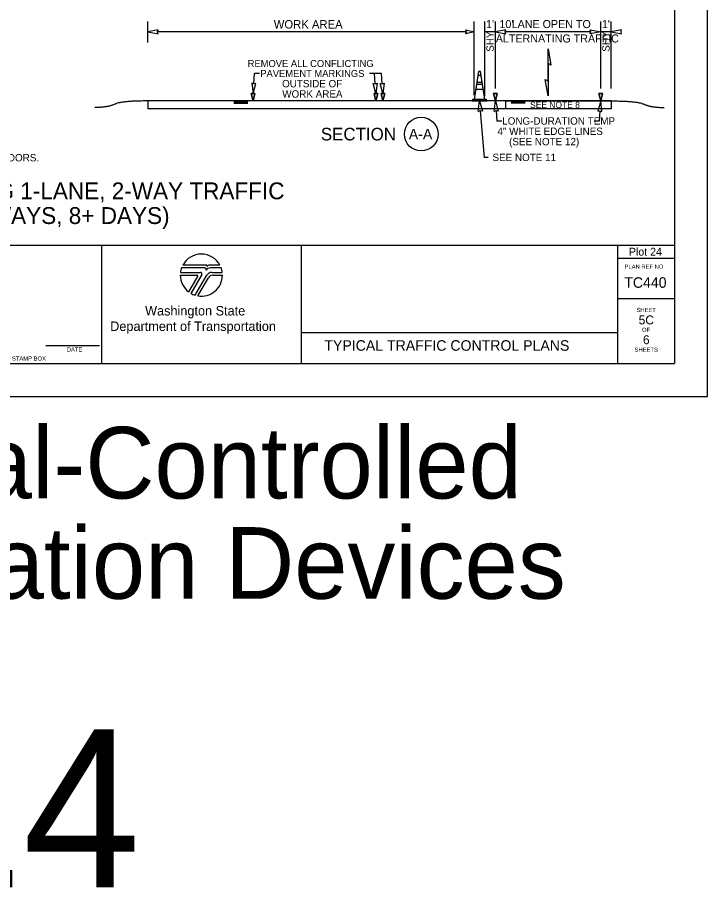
# Model space of a CAD drawing. Extents: x 99982 to 100176, y 99905 to 100011.
# Drawn here: x 100069.51 to 100076.06, y 99935.01 to 99943.29 of the extents above; entities that cross this region are included whole.
import ezdxf

# ---------------------------------------------------------------- set-up
doc = ezdxf.new("R2010")
doc.units = 0
for name, color, linetype in [('SH_DE_DetailHeading1Text', 7, 'Continuous'), ('SH_GI_GeneralNotesBodyText', 7, 'Continuous'), ('SH_GI_PlotLimits', 7, 'Continuous'), ('SH_GI_SheetBorder', 7, 'Continuous'), ('SH_GI_SheetLocationText', 7, 'Continuous'), ('SH_GI_SheetTextInCells', 7, 'Continuous'), ('SH_GI_TitleBlockText', 7, 'Continuous'), ('SH_GI_WSDOTLogo', 7, 'Continuous'), ('TR_WZ_TrafficConeElev', 7, 'Continuous'), ('TR_WZ_WorkZoneDetails', 7, 'Continuous'), ('TR_WZ_WorkZoneTextCurrent', 7, 'Continuous')]:
    doc.layers.add(name, color=color, linetype=linetype)

msp = doc.modelspace()

# ---------------------------------------------------------------- linework, layer by layer
at = {"layer": 'SH_GI_PlotLimits'}
msp.add_lwpolyline([(100059.0625, 99939.6875), (100076.0625, 99939.6875), (100076.0625, 99950.6875), (100059.0625, 99950.6875)], close=True, dxfattribs=at)
at = {"layer": 'SH_GI_SheetBorder'}
for p, q in [((100075.75, 99950.375), (100075.75, 99940)), ((100060, 99941.1259), (100075.75, 99941.1259)), ((100070.3089, 99941.1259), (100070.3089, 99940)), ((100072.2055, 99941.1259), (100072.2055, 99940)), ((100075.2079, 99941.1259), (100075.2079, 99940)), ((100075.2079, 99941.0008), (100075.75, 99941.0008)), ((100075.2079, 99940.6176), (100075.75, 99940.6176)), ((100072.2055, 99940.2955), (100075.2079, 99940.2955)), ((100069.7797, 99940.1733), (100070.2914, 99940.1733)), ((100060, 99940), (100075.75, 99940))]:
    msp.add_line(p, q, dxfattribs=at)
at = {"layer": 'SH_GI_WSDOTLogo'}
for p, q in [((100071.303, 99940.9354), (100071.0815, 99940.9354)), ((100071.433, 99940.9354), (100071.3351, 99940.9354)), ((100071.0572, 99940.84), (100071.2148, 99940.84)), ((100071.059, 99940.8661), (100071.2496, 99940.8661)), ((100071.2894, 99940.9094), (100071.0697, 99940.9094)), ((100071.261, 99940.8464), (100071.1567, 99940.6672)), ((100071.1989, 99940.6487), (100071.3089, 99940.839)), ((100071.343, 99940.9094), (100071.3429, 99940.9094)), ((100071.4448, 99940.9094), (100071.343, 99940.9094)), ((100071.3558, 99940.8661), (100071.4555, 99940.8661)), ((100071.3655, 99940.8394), (100071.4572, 99940.8394)), ((100071.222, 99940.8277), (100071.1364, 99940.6807)), ((100071.2244, 99940.6428), (100071.3242, 99940.8156))]:
    msp.add_line(p, q, dxfattribs=at)
for centre, radius, start, end in [((100071.2572, 99940.84), 0.2, 28.47865, 151.53204), ((100071.303, 99940.9263), 0.00903, 329.87418, 90.00328), ((100071.3352, 99940.9066), 0.0287, 90.00721, 148.16763), ((100071.2572, 99940.84), 0.2, 179.99864, 232.84327), ((100071.2572, 99940.84), 0.2, 159.69598, 172.50569), ((100071.2149, 99940.8318), 0.0082, 329.74356, 90), ((100071.2572, 99940.84), 0.2, 260.54554, 359.80857), ((100071.2497, 99940.853), 0.0131, 329.76834, 90), ((100071.2894, 99940.8946), 0.0148, 327.8418, 89.99855), ((100071.3429, 99940.861), 0.0484, 89.99529, 147.82376), ((100071.3558, 99940.8119), 0.0542, 90, 149.99738), ((100071.3654, 99940.7918), 0.0476, 90, 150.05432), ((100071.2572, 99940.84), 0.2, 7.49431, 20.29406), ((100071.2572, 99940.84), 0.2, 239.79292, 253.0448)]:
    msp.add_arc(centre, radius, start, end, dxfattribs=at)
at = {"layer": 'TR_WZ_TrafficConeElev'}
for p, q in [((100073.8828, 99942.7369), (100073.8728, 99942.6719)), ((100073.8728, 99942.6719), (100073.923, 99942.6719)), ((100073.913, 99942.7369), (100073.8828, 99942.7369)), ((100073.923, 99942.6719), (100073.913, 99942.7369)), ((100073.8697, 99942.6519), (100073.8628, 99942.6069)), ((100073.8628, 99942.6069), (100073.9329, 99942.6069)), ((100073.926, 99942.6519), (100073.8697, 99942.6519)), ((100073.9329, 99942.6069), (100073.926, 99942.6519)), ((100073.8335, 99942.5094), (100073.8285, 99942.5044)), ((100073.8285, 99942.5044), (100073.8285, 99942.4944)), ((100073.8285, 99942.4944), (100073.9673, 99942.4944)), ((100073.8479, 99942.5094), (100073.8335, 99942.5094)), ((100073.9673, 99942.5044), (100073.9623, 99942.5094)), ((100073.9673, 99942.4944), (100073.9673, 99942.5044))]:
    msp.add_line(p, q, dxfattribs=at)
msp.add_lwpolyline([(100073.8479, 99942.5094), (100073.9479, 99942.5094), (100073.9073, 99942.7744), (100073.8885, 99942.7744)], close=True, dxfattribs=at)
msp.add_lwpolyline([(100073.8479, 99942.5094), (100073.9479, 99942.5094), (100073.9073, 99942.7744), (100073.8885, 99942.7744)], close=True, dxfattribs=at)
msp.add_lwpolyline([(100073.9623, 99942.5094), (100073.9479, 99942.5094), (100073.8479, 99942.5094)], dxfattribs=at)
at = {"layer": 'TR_WZ_WorkZoneDetails'}
for p, q in [((100070.7479, 99943.0504), (100070.7479, 99943.2504)), ((100073.8479, 99942.5494), (100073.8479, 99943.2504)), ((100073.9479, 99942.5394), (100073.9479, 99943.2504)), ((100074.0479, 99942.6142), (100074.0479, 99943.2504)), ((100075.0479, 99942.6142), (100075.0479, 99943.2504)), ((100075.1479, 99942.6142), (100075.1479, 99943.2504)), ((100073.7729, 99943.1504), (100070.8416, 99943.1504)), ((100074.0479, 99943.1504), (100073.9479, 99943.1504)), ((100074.9542, 99943.1504), (100074.1416, 99943.1504)), ((100075.1479, 99943.1504), (100075.0479, 99943.1504)), ((100074.5479, 99942.8508), (100074.5479, 99942.682)), ((100074.5479, 99942.682), (100074.5479, 99942.8508)), ((100071.7553, 99942.6576), (100071.763, 99942.7552)), ((100071.8092, 99942.7552), (100071.763, 99942.7552)), ((100072.966, 99942.7552), (100072.8531, 99942.7552)), ((100072.9071, 99942.6576), (100072.8993, 99942.7552)), ((100072.9737, 99942.6576), (100072.966, 99942.7552)), ((100070.7479, 99942.4944), (100070.7479, 99942.4194)), ((100075.1479, 99942.4944), (100070.7479, 99942.4944)), ((100075.1479, 99942.4944), (100075.1479, 99942.4194)), ((100075.1479, 99942.4194), (100070.7479, 99942.4194)), ((100071.5649, 99942.4891), (100071.6979, 99942.4891)), ((100071.5649, 99942.4835), (100071.6979, 99942.4835)), ((100071.5649, 99942.4779), (100071.6979, 99942.4779)), ((100071.5649, 99942.4726), (100071.6979, 99942.4726)), ((100074.3309, 99942.4887), (100074.1979, 99942.4887)), ((100074.3309, 99942.4831), (100074.1979, 99942.4831)), ((100074.3309, 99942.4774), (100074.1979, 99942.4774)), ((100074.3309, 99942.4722), (100074.1979, 99942.4722)), ((100073.9053, 99942.4009), (100073.9406, 99941.9574)), ((100074.0553, 99942.4009), (100074.0631, 99942.3034)), ((100075.0404, 99942.4009), (100075.0327, 99942.3034)), ((100074.1092, 99942.3034), (100074.0631, 99942.3034)), ((100075.0327, 99942.3034), (100074.9865, 99942.3034)), ((100073.9806, 99941.9574), (100073.9406, 99941.9574))]:
    msp.add_line(p, q, dxfattribs=at)
for points in [[(100070.7479, 99943.1504), (100070.8461, 99943.1312), (100070.8416, 99943.1504), (100070.8461, 99943.1697)], [(100073.8479, 99943.1504), (100073.7693, 99943.1312), (100073.7729, 99943.1504), (100073.7693, 99943.1697)], [(100074.0479, 99943.1504), (100074.1462, 99943.1312), (100074.1416, 99943.1504), (100074.1462, 99943.1697)], [(100075.0479, 99943.1504), (100074.9496, 99943.1312), (100074.9542, 99943.1504), (100074.9496, 99943.1697)], [(100075.1479, 99943.1504), (100075.2462, 99943.1312), (100075.2416, 99943.1504), (100075.2462, 99943.1697)], [(100074.5479, 99942.9884), (100074.5749, 99942.8352), (100074.5479, 99942.8508)], [(100071.7478, 99942.5642), (100071.7748, 99942.6606), (100071.7552, 99942.6576), (100071.7363, 99942.6637)], [(100072.9145, 99942.5642), (100072.8875, 99942.6606), (100072.9071, 99942.6576), (100072.926, 99942.6637)], [(100072.9812, 99942.5642), (100072.9542, 99942.6606), (100072.9738, 99942.6576), (100072.9926, 99942.6637)], [(100074.5479, 99942.5444), (100074.5209, 99942.6976), (100074.5479, 99942.682)], [(100071.7479, 99942.4944), (100071.7312, 99942.5642), (100071.7645, 99942.5642)], [(100072.9145, 99942.4944), (100072.8978, 99942.5642), (100072.9312, 99942.5642)], [(100072.9812, 99942.4944), (100072.9645, 99942.5642), (100072.9978, 99942.5642)], [(100073.8979, 99942.4944), (100073.9248, 99942.3979), (100073.9053, 99942.4009), (100073.8864, 99942.3949)], [(100074.0479, 99942.4944), (100074.0312, 99942.5642), (100074.0645, 99942.5642)], [(100074.0479, 99942.4944), (100074.0748, 99942.3979), (100074.0553, 99942.4009), (100074.0364, 99942.3949)], [(100074.1479, 99942.4944), (100075.1479, 99942.4944), (100075.1479, 99942.4194), (100074.1479, 99942.4194)], [(100074.1479, 99942.4944), (100075.1479, 99942.4944), (100075.1479, 99942.4194), (100074.1479, 99942.4194)], [(100075.0479, 99942.4944), (100075.0209, 99942.3979), (100075.0405, 99942.4009), (100075.0593, 99942.3949)], [(100075.0479, 99942.4944), (100075.0312, 99942.5642), (100075.0645, 99942.5642)]]:
    msp.add_lwpolyline(points, close=True, dxfattribs=at)
for points in [[(100071.7645, 99942.5642), (100071.7312, 99942.5642), (100071.7479, 99942.4944), (100071.7645, 99942.5642)], [(100072.9312, 99942.5642), (100072.8978, 99942.5642), (100072.9145, 99942.4944), (100072.9312, 99942.5642)], [(100072.9978, 99942.5642), (100072.9645, 99942.5642), (100072.9812, 99942.4944), (100072.9978, 99942.5642)], [(100074.0645, 99942.5642), (100074.0312, 99942.5642), (100074.0479, 99942.4944), (100074.0645, 99942.5642)], [(100075.0645, 99942.5642), (100075.0312, 99942.5642), (100075.0479, 99942.4944), (100075.0645, 99942.5642)]]:
    msp.add_lwpolyline(points, dxfattribs=at)
msp.add_circle((100073.3444, 99942.1794), 0.16, dxfattribs=at)
for points in [[(100070.7479, 99942.4944), (100070.4967, 99942.4944), (100070.3712, 99942.4322), (100070.2457, 99942.4322)], [(100075.1479, 99942.4944), (100075.399, 99942.4945), (100075.5245, 99942.4324), (100075.65, 99942.4325)]]:
    msp.add_open_spline(points, degree=2, dxfattribs=at)

# ---------------------------------------------------------------- texts
at = {"layer": 'SH_DE_DetailHeading1Text'}
for s, p in [('ADVANCED TEMPORARY SIGNAL-CONTROLLED ALTERNATING 1-LANE, 2-WAY TRAFFIC', (100062.9401, 99941.5606)), ('25 WZSL + CHANNELIZING DEVICES (30 MPH HIGHWAYS, 8+ DAYS)', (100064.0241, 99941.3259))]:
    msp.add_text(s, height=0.16, rotation=360, dxfattribs=at).set_placement(p)
at = {"layer": 'SH_GI_GeneralNotesBodyText'}
msp.add_text('ROADWAY WIDTH RESTRICTIONS. 30 DAY NOTICE REQUIRED ON MAJOR FREIGHT CORRIDORS.', height=0.07, rotation=360, dxfattribs=at).set_placement((100065.3222, 99941.9206))
at = {"layer": 'SH_GI_SheetBorder'}
msp.add_text('PLAN REF NO', height=0.040032, dxfattribs=at).set_placement((100075.2747, 99940.9008))
at = {"layer": 'SH_GI_SheetLocationText'}
for s, height, p in [('Plot 24', 0.075, (100075.3164, 99941.025)), (' Temp Signal-Controlled', 0.68, (100064.4951, 99938.7191)), ('Alt Traffic w/ Channelization Devices', 0.68, (100059.9592, 99937.7671)), ('Plot 24', 1.5, (100064.4341, 99935.0267))]:
    msp.add_text(s, height=height, dxfattribs=at).set_placement(p)
at = {"layer": 'SH_GI_SheetTextInCells'}
for s, height, p in [('Washington State', 0.090072, (100070.7229, 99940.4571)), ('SHEET', 0.04003, (100075.3877, 99940.4896)), ('Department of Transportation', 0.090072, (100070.3916, 99940.3101)), ('OF', 0.04003, (100075.4406, 99940.3008)), ('DATE', 0.04003, (100069.9794, 99940.1141)), ('SHEETS', 0.04003, (100075.3698, 99940.112)), ('P.E. STAMP BOX', 0.040032, (100069.339, 99940.0286))]:
    msp.add_text(s, height=height, dxfattribs=at).set_placement(p)
at = {"layer": 'SH_GI_TitleBlockText'}
for s, height, p in [('TC440', 0.1, (100075.2718, 99940.72)), ('5C', 0.085, (100075.4084, 99940.3723)), ('6', 0.085, (100075.4493, 99940.1843)), ('TYPICAL TRAFFIC CONTROL PLANS', 0.1, (100072.4251, 99940.1224))]:
    msp.add_text(s, height=height, dxfattribs=at).set_placement(p)
at = {"layer": 'TR_WZ_WorkZoneDetails'}
for s, height, p in [('WORK AREA', 0.08, (100071.9443, 99943.1824)), ("1'", 0.076, (100073.9599, 99943.1864)), ("10'", 0.076, (100074.0867, 99943.1864)), (' LANE OPEN TO', 0.076, (100074.1748, 99943.1864)), ("1'", 0.076, (100075.0595, 99943.1864)), ('ALTERNATING TRAFFIC', 0.076, (100074.0522, 99943.0496))]:
    msp.add_text(s, height=height, dxfattribs=at).set_placement(p)
for s, height, rotation, p in [('SHY', 0.07, 90, (100074.0329, 99942.9617)), ('SHY', 0.07, 90, (100075.1329, 99942.9617)), ('SECTION', 0.12, 360, (100072.3913, 99942.1194)), ('A-A', 0.1, 360, (100073.2265, 99942.1294))]:
    msp.add_text(s, height=height, rotation=rotation, dxfattribs=at).set_placement(p)
at = {"layer": 'TR_WZ_WorkZoneTextCurrent'}
for s, height, p in [('REMOVE ALL CONFLICTING', 0.0665, (100071.6969, 99942.8164)), ('PAVEMENT MARKINGS', 0.0665, (100071.8168, 99942.7219)), ('OUTSIDE OF', 0.07, (100072.0233, 99942.6239)), ('WORK AREA', 0.07, (100072.0253, 99942.5259)), ('SEE NOTE 8', 0.06, (100074.3778, 99942.4269)), ('LONG-DURATION TEMP', 0.07, (100074.1132, 99942.2694)), ('4" WHITE EDGE LINES', 0.07, (100074.068, 99942.1714)), ('(SEE NOTE 12)', 0.07, (100074.1784, 99942.0734)), ('SEE NOTE 11', 0.07, (100074.0206, 99941.9234))]:
    msp.add_text(s, height=height, dxfattribs=at).set_placement(p)

doc.saveas('drawing.dxf')
